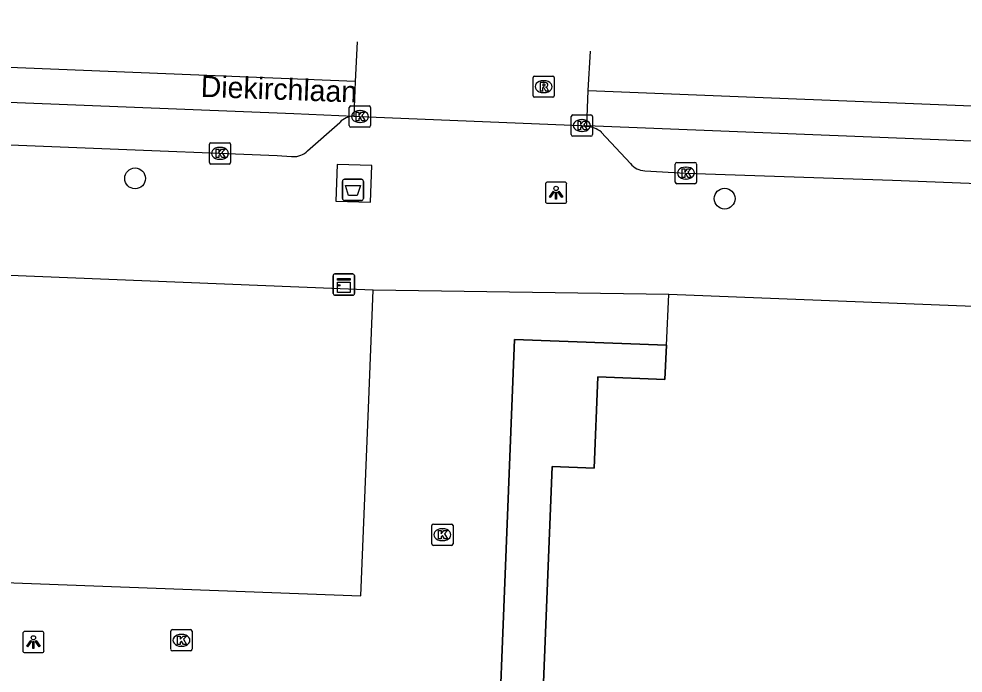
# Model space of a CAD drawing. Extents: x 160891 to 161384, y 386490 to 386907.
# Drawn here: x 161096.46 to 161140.9, y 386873.15 to 386903.93 of the extents above; entities that cross this region are included whole.
import ezdxf

# ---------------------------------------------------------------- set-up
doc = ezdxf.new("R2010")
doc.units = 0
for name, color, linetype in [('IMGEO_Afval_apart_plaats', 7, 'Continuous'), ('IMGEO_Boom', 7, 'Continuous'), ('IMGEO_Kast', 7, 'Continuous'), ('IMGEO_Kolk', 7, 'Continuous'), ('IMGEO_Lichtpunt', 7, 'Continuous'), ('IMGEO_Openbare_ruimte_label', 7, 'Continuous'), ('IMGEO_Pand', 7, 'Continuous'), ('IMGEO_Pand_overbouw', 7, 'Continuous'), ('IMGEO_Rijbaan_lokaal_gesloten', 7, 'Continuous'), ('IMGEO_Rioolput', 7, 'Continuous'), ('IMGEO_Voetpad_gesloten', 7, 'Continuous'), ('IMGEO_Voetpad_open', 7, 'Continuous')]:
    doc.layers.add(name, color=color, linetype=linetype)

msp = doc.modelspace()

# ---------------------------------------------------------------- linework, layer by layer
at = {"layer": 'IMGEO_Afval_apart_plaats'}
for p, q in [((161111.692, 386895.485), (161111.692, 386896.285)), ((161111.692, 386896.285), (161111.692, 386895.485)), ((161111.792, 386896.385), (161112.582, 386896.385)), ((161112.582, 386896.385), (161111.792, 386896.385)), ((161112.682, 386896.285), (161112.682, 386895.485)), ((161112.682, 386895.485), (161112.682, 386896.285)), ((161112.582, 386895.385), (161111.792, 386895.385)), ((161111.792, 386895.385), (161112.582, 386895.385))]:
    msp.add_line(p, q, dxfattribs=at)
msp.add_lwpolyline([(161111.835, 386896.099), (161112.539, 386896.099), (161112.39, 386895.629), (161111.984, 386895.629), (161111.835, 386896.099)], dxfattribs=at)
for centre, start, end in [((161111.792, 386896.285), 90, 180), ((161111.792, 386896.285), 90, 180), ((161112.582, 386896.285), 0, 90), ((161112.582, 386896.285), 360, 90), ((161111.792, 386895.485), 180, 270), ((161111.792, 386895.485), 180, 270), ((161112.582, 386895.485), 270, 0), ((161112.582, 386895.485), 270, 0)]:
    msp.add_arc(centre, 0.1, start, end, dxfattribs=at)
at = {"layer": 'IMGEO_Boom'}
for centre in [(161101.933, 386896.429), (161129.681, 386895.476)]:
    msp.add_circle(centre, 0.489, dxfattribs=at)
at = {"layer": 'IMGEO_Kast'}
for p, q in [((161111.258, 386891.006), (161111.258, 386891.847)), ((161111.258, 386891.847), (161111.258, 386891.006)), ((161111.333, 386891.931), (161112.174, 386891.931)), ((161112.174, 386891.931), (161111.333, 386891.931)), ((161112.258, 386891.856), (161112.258, 386891.015)), ((161112.258, 386891.015), (161112.258, 386891.856)), ((161112.183, 386890.931), (161111.342, 386890.931)), ((161111.342, 386890.931), (161112.183, 386890.931))]:
    msp.add_line(p, q, dxfattribs=at)
for points in [[(161111.453, 386891.721), (161112.053, 386891.721), (161112.053, 386891.636), (161111.453, 386891.636), (161111.453, 386891.721)], [(161111.453, 386891.546), (161112.053, 386891.546), (161112.053, 386891.057), (161111.453, 386891.057), (161111.453, 386891.546)]]:
    msp.add_lwpolyline(points, dxfattribs=at)
msp.add_circle((161111.537, 386891.395), 0.0377, dxfattribs=at)
for centre, start, end in [((161111.336, 386891.853), 92.4484, 184.2845), ((161111.336, 386891.853), 92.4484, 184.2845), ((161112.18, 386891.853), 2.4484, 94.2845), ((161112.18, 386891.853), 2.4484, 94.2845), ((161111.336, 386891.009), 182.4484, 274.2845), ((161111.336, 386891.009), 182.4484, 274.2845), ((161112.18, 386891.009), 272.4484, 4.2845), ((161112.18, 386891.009), 272.4484, 4.2845)]:
    msp.add_arc(centre, 0.0779, start, end, dxfattribs=at)
at = {"layer": 'IMGEO_Kolk'}
for p, q in [((161112.091, 386899.84), (161112.943, 386899.84)), ((161112.016, 386898.914), (161112.016, 386899.766)), ((161112.504, 386899.62), (161112.529, 386899.62)), ((161113.017, 386899.766), (161113.017, 386898.914)), ((161122.534, 386899.416), (161123.386, 386899.416)), ((161112.527, 386899.06), (161112.502, 386899.06)), ((161122.459, 386898.49), (161122.459, 386899.342)), ((161122.947, 386899.196), (161122.972, 386899.196)), ((161123.46, 386899.342), (161123.46, 386898.49)), ((161112.943, 386898.84), (161112.091, 386898.84)), ((161122.97, 386898.636), (161122.945, 386898.636)), ((161105.43, 386897.18), (161105.43, 386898.032)), ((161105.505, 386898.106), (161106.357, 386898.106)), ((161106.431, 386898.032), (161106.431, 386897.18)), ((161123.386, 386898.416), (161122.534, 386898.416)), ((161105.918, 386897.886), (161105.943, 386897.886)), ((161105.941, 386897.326), (161105.916, 386897.326)), ((161127.433, 386897.178), (161128.285, 386897.178)), ((161106.357, 386897.106), (161105.505, 386897.106)), ((161127.358, 386896.252), (161127.358, 386897.104)), ((161127.846, 386896.958), (161127.871, 386896.958)), ((161128.359, 386897.104), (161128.359, 386896.252)), ((161127.869, 386896.398), (161127.844, 386896.398)), ((161128.285, 386896.178), (161127.433, 386896.178)), ((161115.896, 386879.235), (161115.896, 386880.087)), ((161115.971, 386880.161), (161116.823, 386880.161)), ((161116.384, 386879.941), (161116.409, 386879.941)), ((161116.897, 386880.087), (161116.897, 386879.235)), ((161116.407, 386879.381), (161116.382, 386879.381)), ((161116.823, 386879.161), (161115.971, 386879.161)), ((161103.615, 386874.267), (161103.615, 386875.119)), ((161103.69, 386875.193), (161104.542, 386875.193)), ((161104.103, 386874.973), (161104.128, 386874.973)), ((161104.616, 386875.119), (161104.616, 386874.267)), ((161104.542, 386874.193), (161103.69, 386874.193)), ((161104.126, 386874.413), (161104.101, 386874.413))]:
    msp.add_line(p, q, dxfattribs=at)
for points in [[(161112.091, 386899.84), (161112.943, 386899.84)], [(161112.016, 386898.914), (161112.016, 386899.766)], [(161112.337, 386899.54), (161112.46, 386899.54), (161112.46, 386899.389), (161112.59, 386899.54), (161112.754, 386899.54), (161112.608, 386899.389), (161112.761, 386899.14), (161112.609, 386899.14), (161112.524, 386899.304), (161112.46, 386899.237), (161112.46, 386899.14), (161112.337, 386899.14), (161112.337, 386899.54)], [(161113.017, 386899.766), (161113.017, 386898.914)], [(161122.534, 386899.416), (161123.386, 386899.416)], [(161122.459, 386898.49), (161122.459, 386899.342)], [(161122.78, 386899.116), (161122.903, 386899.116), (161122.903, 386898.965), (161123.033, 386899.116), (161123.197, 386899.116), (161123.051, 386898.965), (161123.204, 386898.716), (161123.052, 386898.716), (161122.967, 386898.88), (161122.903, 386898.813), (161122.903, 386898.716), (161122.78, 386898.716), (161122.78, 386899.116)], [(161123.46, 386899.342), (161123.46, 386898.49)], [(161112.943, 386898.84), (161112.091, 386898.84)], [(161105.43, 386897.18), (161105.43, 386898.032)], [(161105.505, 386898.106), (161106.357, 386898.106)], [(161106.431, 386898.032), (161106.431, 386897.18)], [(161123.386, 386898.416), (161122.534, 386898.416)], [(161105.751, 386897.806), (161105.874, 386897.806), (161105.874, 386897.655), (161106.004, 386897.806), (161106.168, 386897.806), (161106.022, 386897.655), (161106.175, 386897.406), (161106.023, 386897.406), (161105.938, 386897.57), (161105.874, 386897.503), (161105.874, 386897.406), (161105.751, 386897.406), (161105.751, 386897.806)], [(161127.433, 386897.178), (161128.285, 386897.178)], [(161106.357, 386897.106), (161105.505, 386897.106)], [(161127.358, 386896.252), (161127.358, 386897.104)], [(161127.679, 386896.878), (161127.802, 386896.878), (161127.802, 386896.727), (161127.932, 386896.878), (161128.096, 386896.878), (161127.95, 386896.727), (161128.103, 386896.478), (161127.951, 386896.478), (161127.866, 386896.642), (161127.802, 386896.575), (161127.802, 386896.478), (161127.679, 386896.478), (161127.679, 386896.878)], [(161128.359, 386897.104), (161128.359, 386896.252)], [(161128.285, 386896.178), (161127.433, 386896.178)], [(161115.896, 386879.235), (161115.896, 386880.087)], [(161115.971, 386880.161), (161116.823, 386880.161)], [(161116.217, 386879.861), (161116.34, 386879.861), (161116.34, 386879.71), (161116.47, 386879.861), (161116.634, 386879.861), (161116.488, 386879.71), (161116.641, 386879.461), (161116.489, 386879.461), (161116.404, 386879.625), (161116.34, 386879.558), (161116.34, 386879.461), (161116.217, 386879.461), (161116.217, 386879.861)], [(161116.897, 386880.087), (161116.897, 386879.235)], [(161116.823, 386879.161), (161115.971, 386879.161)], [(161103.615, 386874.267), (161103.615, 386875.119)], [(161103.69, 386875.193), (161104.542, 386875.193)], [(161104.616, 386875.119), (161104.616, 386874.267)], [(161103.936, 386874.893), (161104.059, 386874.893), (161104.059, 386874.742), (161104.189, 386874.893), (161104.353, 386874.893), (161104.207, 386874.742), (161104.36, 386874.493), (161104.208, 386874.493), (161104.123, 386874.657), (161104.059, 386874.59), (161104.059, 386874.493), (161103.936, 386874.493), (161103.936, 386874.893)], [(161104.542, 386874.193), (161103.69, 386874.193)]]:
    msp.add_lwpolyline(points, dxfattribs=at)
for centre, start, end in [((161112.093, 386899.764), 91.552, 178.448), ((161112.093, 386899.764), 91.552, 178.448), ((161112.941, 386899.764), 1.552, 88.448), ((161112.941, 386899.764), 1.552, 88.448), ((161122.536, 386899.34), 91.552, 178.448), ((161122.536, 386899.34), 91.552, 178.448), ((161123.384, 386899.34), 1.552, 88.448), ((161123.384, 386899.34), 1.552, 88.448), ((161112.093, 386898.916), 181.552, 268.448), ((161112.093, 386898.916), 181.552, 268.448), ((161112.941, 386898.916), 271.552, 358.448), ((161112.941, 386898.916), 271.552, 358.448), ((161122.536, 386898.492), 181.552, 268.448), ((161122.536, 386898.492), 181.552, 268.448), ((161123.384, 386898.492), 271.552, 358.448), ((161123.384, 386898.492), 271.552, 358.448), ((161105.507, 386898.03), 91.552, 178.448), ((161105.507, 386898.03), 91.552, 178.448), ((161106.355, 386898.03), 1.552, 88.448), ((161106.355, 386898.03), 1.552, 88.448), ((161105.507, 386897.182), 181.552, 268.448), ((161105.507, 386897.182), 181.552, 268.448), ((161106.355, 386897.182), 271.552, 358.448), ((161106.355, 386897.182), 271.552, 358.448), ((161127.435, 386897.102), 91.552, 178.448), ((161127.435, 386897.102), 91.552, 178.448), ((161128.283, 386897.102), 1.552, 88.448), ((161128.283, 386897.102), 1.552, 88.448), ((161127.435, 386896.254), 181.552, 268.448), ((161127.435, 386896.254), 181.552, 268.448), ((161128.283, 386896.254), 271.552, 358.448), ((161128.283, 386896.254), 271.552, 358.448), ((161115.973, 386880.085), 91.552, 178.448), ((161115.973, 386880.085), 91.552, 178.448), ((161116.821, 386880.085), 1.552, 88.448), ((161116.821, 386880.085), 1.552, 88.448), ((161115.973, 386879.237), 181.552, 268.448), ((161115.973, 386879.237), 181.552, 268.448), ((161116.821, 386879.237), 271.552, 358.448), ((161116.821, 386879.237), 271.552, 358.448), ((161103.692, 386875.117), 91.552, 178.448), ((161103.692, 386875.117), 91.552, 178.448), ((161104.54, 386875.117), 1.552, 88.448), ((161104.54, 386875.117), 1.552, 88.448), ((161103.692, 386874.269), 181.552, 268.448), ((161103.692, 386874.269), 181.552, 268.448), ((161104.54, 386874.269), 271.552, 358.448), ((161104.54, 386874.269), 271.552, 358.448)]:
    msp.add_arc(centre, 0.0765, start, end, dxfattribs=at)
for centre, major_axis, ratio, start_param, end_param in [((161112.503, 386899.34), (-0.387, 0.002), 0.722429, 4.712389, 7.853982), ((161112.528, 386899.34), (-0.39, 0.002), 0.717154, 1.570796, 4.712389), ((161122.946, 386898.916), (-0.387, 0.002), 0.722429, 4.712389, 7.853982), ((161122.971, 386898.916), (-0.39, 0.002), 0.717154, 1.570796, 4.712389), ((161105.917, 386897.606), (-0.387, 0.002), 0.722429, 4.712389, 7.853982), ((161105.942, 386897.606), (-0.39, 0.002), 0.717154, 1.570796, 4.712389), ((161127.845, 386896.678), (-0.387, 0.002), 0.722429, 4.712389, 7.853982), ((161127.87, 386896.678), (-0.39, 0.002), 0.717154, 1.570796, 4.712389), ((161116.383, 386879.661), (-0.387, 0.002), 0.722429, 4.712389, 7.853982), ((161116.408, 386879.661), (-0.39, 0.002), 0.717154, 1.570796, 4.712389), ((161104.102, 386874.693), (-0.387, 0.002), 0.722429, 4.712389, 7.853982), ((161104.127, 386874.693), (-0.39, 0.002), 0.717154, 1.570796, 4.712389)]:
    msp.add_ellipse(centre, major_axis=major_axis, ratio=ratio, start_param=start_param, end_param=end_param, dxfattribs=at)
at = {"layer": 'IMGEO_Lichtpunt'}
for p, q in [((161122.151, 386896.255), (161121.343, 386896.255)), ((161122.151, 386896.255), (161121.343, 386896.255)), ((161121.249, 386896.16), (161121.249, 386895.353)), ((161121.249, 386896.16), (161121.249, 386895.353)), ((161122.245, 386895.353), (161122.245, 386896.16)), ((161122.245, 386895.353), (161122.245, 386896.16)), ((161121.343, 386895.259), (161122.151, 386895.259)), ((161121.343, 386895.259), (161122.151, 386895.259)), ((161096.65, 386875.012), (161096.65, 386874.205)), ((161096.65, 386875.012), (161096.65, 386874.205)), ((161097.552, 386875.107), (161096.744, 386875.107)), ((161097.552, 386875.107), (161096.744, 386875.107)), ((161097.646, 386874.205), (161097.646, 386875.012)), ((161097.646, 386874.205), (161097.646, 386875.012)), ((161096.744, 386874.111), (161097.552, 386874.111)), ((161096.744, 386874.111), (161097.552, 386874.111))]:
    msp.add_line(p, q, dxfattribs=at)
for points in [[(161121.623, 386895.824), (161121.662, 386895.796), (161121.474, 386895.534), (161121.436, 386895.561), (161121.623, 386895.824)], [(161121.835, 386895.796), (161121.873, 386895.823), (161122.06, 386895.561), (161122.021, 386895.533), (161121.835, 386895.796)], [(161121.725, 386895.776), (161121.772, 386895.776), (161121.772, 386895.454), (161121.725, 386895.454), (161121.725, 386895.776)], [(161097.024, 386874.676), (161097.063, 386874.648), (161096.875, 386874.386), (161096.837, 386874.413), (161097.024, 386874.676)], [(161097.126, 386874.628), (161097.173, 386874.628), (161097.173, 386874.306), (161097.126, 386874.306), (161097.126, 386874.628)], [(161097.236, 386874.648), (161097.274, 386874.675), (161097.461, 386874.413), (161097.422, 386874.385), (161097.236, 386874.648)]]:
    msp.add_lwpolyline(points, dxfattribs=at)
for centre in [(161121.748, 386895.958), (161097.149, 386874.81)]:
    msp.add_circle(centre, 0.0994, dxfattribs=at)
for centre, start, end in [((161121.343, 386896.16), 90, 180), ((161121.343, 386896.16), 90, 180), ((161122.151, 386896.16), 0, 90), ((161122.151, 386896.16), 0, 90), ((161121.343, 386895.353), 180, 270), ((161121.343, 386895.353), 180, 270), ((161122.151, 386895.353), 270, 0), ((161122.151, 386895.353), 270, 360), ((161096.744, 386875.012), 90, 180), ((161096.744, 386875.012), 90, 180), ((161097.552, 386875.012), 0, 90), ((161097.552, 386875.012), 0, 90), ((161096.744, 386874.205), 180, 270), ((161096.744, 386874.205), 180, 270), ((161097.552, 386874.205), 270, 0), ((161097.552, 386874.205), 270, 360)]:
    msp.add_arc(centre, 0.0946, start, end, dxfattribs=at)
at = {"layer": 'IMGEO_Pand'}
for points in [[(161113.143, 386891.17), (161097.194, 386891.813), (161080.645, 386892.481), (161055.667, 386893.489), (161046.293, 386893.867), (161046.299, 386893.997), (161046.043, 386894.008)], [(161073.594, 386878.249), (161112.563, 386876.783), (161112.919, 386885.615), (161113.143, 386891.17)], [(161126.941, 386888.577), (161127.058, 386890.969)], [(161196.381, 386887.886), (161196.395, 386888.23), (161188.186, 386888.554), (161178.427, 386888.94), (161127.058, 386890.969)], [(161126.941, 386888.577), (161126.862, 386886.972), (161123.715, 386887.092), (161123.545, 386882.788), (161121.567, 386882.869), (161121.073, 386870.746), (161120.711, 386870.76), (161120.682, 386870.014), (161121.042, 386870), (161120.551, 386857.609)]]:
    msp.add_lwpolyline(points, dxfattribs=at)
at = {"layer": 'IMGEO_Pand_overbouw'}
msp.add_lwpolyline([(161120.551, 386857.609), (161121.042, 386870), (161120.682, 386870.014), (161120.711, 386870.76), (161121.073, 386870.746), (161121.567, 386882.869), (161123.545, 386882.788), (161123.715, 386887.092), (161126.862, 386886.972), (161126.941, 386888.577), (161119.79, 386888.855), (161118.549, 386857.687), (161118.629, 386857.684)], close=True, dxfattribs=at)
at = {"layer": 'IMGEO_Rijbaan_lokaal_gesloten'}
for points in [[(161112.299, 386900.982), (161040.205, 386903.901), (161035.665, 386902.345), (160996.157, 386903.935)], [(161112.38, 386902.848), (161112.299, 386900.982)], [(161123.263, 386900.56), (161123.374, 386902.409)], [(161073.486, 386900.908), (161109.397, 386899.476), (161112.234, 386899.353)], [(161112.299, 386900.982), (161112.234, 386899.353)], [(161123.188, 386898.901), (161123.263, 386900.56)], [(161123.263, 386900.56), (161248.069, 386895.57), (161278.544, 386894.358), (161279.11, 386894.349)], [(161112.234, 386899.353), (161112.26, 386899.352), (161112.517, 386899.34), (161122.897, 386898.919)], [(161122.897, 386898.919), (161122.96, 386898.916), (161123.188, 386898.901)], [(161155.904, 386897.594), (161123.188, 386898.901)]]:
    msp.add_lwpolyline(points, dxfattribs=at)
at = {"layer": 'IMGEO_Rioolput'}
for p, q in [((161120.662, 386900.32), (161120.662, 386901.172)), ((161120.737, 386901.246), (161121.589, 386901.246)), ((161121.663, 386901.172), (161121.663, 386900.32)), ((161121.15, 386901.026), (161121.175, 386901.026)), ((161121.173, 386900.466), (161121.148, 386900.466)), ((161121.589, 386900.246), (161120.737, 386900.246))]:
    msp.add_line(p, q, dxfattribs=at)
for points in [[(161120.662, 386900.32), (161120.662, 386901.172)], [(161120.737, 386901.246), (161121.589, 386901.246)], [(161121.663, 386901.172), (161121.663, 386900.32)], [(161121.251, 386900.944), (161120.999, 386900.946), (161120.999, 386900.546)], [(161120.999, 386900.546), (161121.123, 386900.546), (161121.123, 386900.708), (161121.134, 386900.708)], [(161121.177, 386900.865), (161121.123, 386900.865), (161121.123, 386900.784)], [(161121.123, 386900.784), (161121.175, 386900.784)], [(161121.181, 386900.679), (161121.252, 386900.546), (161121.392, 386900.546), (161121.327, 386900.672)], [(161121.589, 386900.246), (161120.737, 386900.246)]]:
    msp.add_lwpolyline(points, dxfattribs=at)
for centre, radius, start, end in [((161120.739, 386901.17), 0.0765, 91.552, 178.448), ((161120.739, 386901.17), 0.0765, 91.552, 178.448), ((161121.587, 386901.17), 0.0765, 1.552, 88.448), ((161121.587, 386901.17), 0.0765, 1.552, 88.448), ((161121.133, 386900.655), 0.0533, 26.0293, 88.6989), ((161121.159, 386900.973), 0.19, 274.7715, 282.9687), ((161121.183, 386900.769), 0.0964, 77.0061, 93.1865), ((161121.197, 386900.826), 0.0378, 276.6634, 79.6772), ((161121.25, 386900.834), 0.109, 350.3612, 89.416), ((161121.248, 386900.834), 0.112, 277.5842, 350.9817), ((161121.232, 386900.619), 0.108, 29.5134, 73.7905), ((161120.739, 386900.322), 0.0765, 181.552, 268.448), ((161120.739, 386900.322), 0.0765, 181.552, 268.448), ((161121.587, 386900.322), 0.0765, 271.552, 358.448), ((161121.587, 386900.322), 0.0765, 271.552, 358.448)]:
    msp.add_arc(centre, radius, start, end, dxfattribs=at)
for centre, major_axis, ratio, start_param, end_param in [((161121.149, 386900.746), (-0.387, 0.002), 0.722429, 4.712389, 7.853982), ((161121.174, 386900.746), (-0.39, 0.002), 0.717154, 1.570796, 4.712389)]:
    msp.add_ellipse(centre, major_axis=major_axis, ratio=ratio, start_param=start_param, end_param=end_param, dxfattribs=at)
at = {"layer": 'IMGEO_Voetpad_gesloten'}
msp.add_lwpolyline([(161111.443, 386897.079), (161111.388, 386895.362), (161113.02, 386895.309), (161113.076, 386897.03), (161111.443, 386897.079)], dxfattribs=at)
at = {"layer": 'IMGEO_Voetpad_open'}
for points in [[(161073.403, 386898.925), (161074.03, 386898.891), (161108.628, 386897.506), (161109.298, 386897.46), (161109.361, 386897.456)], [(161110.048, 386897.723), (161111.567, 386899.063)], [(161122.897, 386898.919), (161123.175, 386898.874)], [(161123.877, 386898.605), (161125.249, 386897.126)], [(161125.921, 386896.787), (161127.859, 386896.678), (161137.577, 386896.347), (161155.616, 386895.637)], [(161127.058, 386890.969), (161113.143, 386891.17)], [(161118.549, 386857.687), (161119.79, 386888.855), (161126.941, 386888.577)]]:
    msp.add_lwpolyline(points, dxfattribs=at)
for centre, radius, start, end in [((161112.22, 386898.474), 0.879, 89.0729, 137.9243), ((161123.116, 386897.668), 1.207, 50.89, 87.1773), ((161109.409, 386898.35), 0.896, 266.9377, 315.5391), ((161125.945, 386897.669), 0.883, 217.9927, 268.4686)]:
    msp.add_arc(centre, radius, start, end, dxfattribs=at)

# ---------------------------------------------------------------- texts
at = {"layer": 'IMGEO_Openbare_ruimte_label'}
msp.add_text('Diekirchlaan', height=1, rotation=357.8789, dxfattribs=at).set_placement((161105.012, 386900.269))

doc.saveas('drawing.dxf')
